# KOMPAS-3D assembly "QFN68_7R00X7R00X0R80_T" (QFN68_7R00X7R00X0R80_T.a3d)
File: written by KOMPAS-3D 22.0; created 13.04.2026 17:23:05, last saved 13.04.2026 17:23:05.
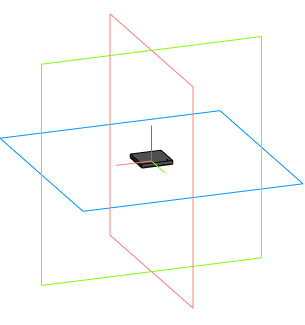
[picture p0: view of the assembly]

Document properties: Автор: Andrey; Полное имя файла: C:\Users\User1\Documents\QFN68_7R00X7R00X0R80_T.a3d

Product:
- Component [detail]: RK806-1  | qty 1  | source file: RK806-1.m3d
- Part/product: QFN68_7R00X7R00X0R80_T
    Комментарий: QFN68_7R00X7R00X0R80_T

Referenced files in C:\Users\User1\Documents\: RK806-1.m3d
